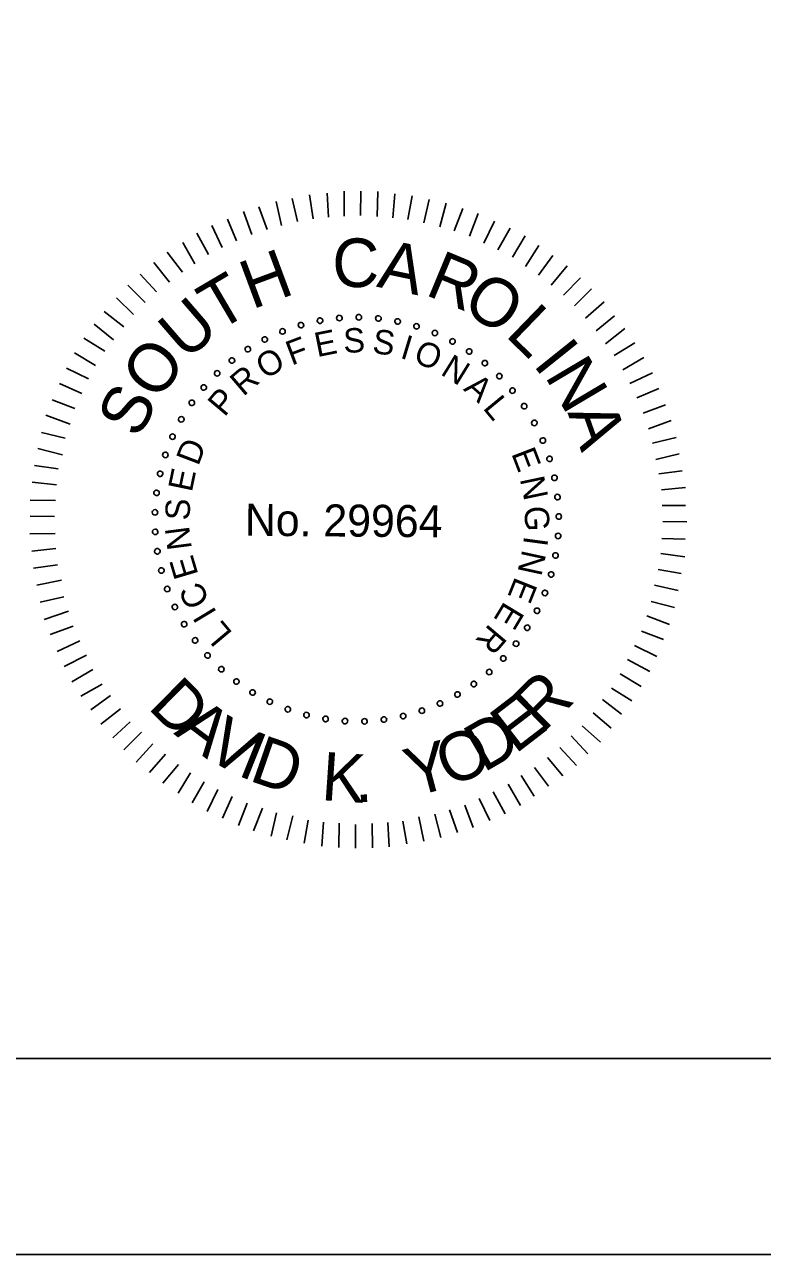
# Model space of a CAD drawing. Extents: x -146.3 to -98.2, y -113.4 to -84.1.
# Drawn here: x -115.032 to -112.521, y -113.391 to -109.207 of the extents above; entities that cross this region are included whole.
import ezdxf

# ---------------------------------------------------------------- set-up
doc = ezdxf.new("R2010")
doc.units = 0
for name, color, linetype in [('BR_BORDER LINES', 7, 'Continuous'), ('BR_TEXT', 7, 'Continuous'), ('Level 31', 7, 'Continuous')]:
    doc.layers.add(name, color=color, linetype=linetype)

msp = doc.modelspace()

# ---------------------------------------------------------------- linework, layer by layer
at = {"layer": 'BR_BORDER LINES'}
msp.add_line((-143.8657, -112.7249), (-98.9787, -112.7249), dxfattribs=at)
at = {"layer": 'BR_TEXT'}
for p, q in [((-114.1028, -109.8773), (-114.1216, -109.7981)), ((-114.0501, -109.8674), (-114.062, -109.7861)), ((-113.9974, -109.8621), (-114.0024, -109.7808)), ((-113.9447, -109.8591), (-113.944, -109.7733)), ((-113.8886, -109.8562), (-113.888, -109.7738)), ((-113.8326, -109.86), (-113.8296, -109.7742)), ((-113.7789, -109.8639), (-113.7725, -109.7827)), ((-113.7274, -109.8701), (-113.713, -109.789)), ((-113.6737, -109.8808), (-113.6548, -109.802)), ((-114.2588, -109.9206), (-114.2867, -109.8426)), ((-114.206, -109.9038), (-114.2351, -109.827)), ((-114.1578, -109.8905), (-114.1754, -109.8092)), ((-113.6189, -109.895), (-113.5976, -109.8139)), ((-113.5699, -109.9091), (-113.5406, -109.8327)), ((-114.3104, -109.9431), (-114.3418, -109.8684)), ((-113.5173, -109.9267), (-113.4881, -109.8491)), ((-113.4695, -109.95), (-113.4323, -109.8759)), ((-114.4058, -109.9892), (-114.4463, -109.9168)), ((-114.3598, -109.9655), (-114.3947, -109.8909)), ((-113.4216, -109.9733), (-113.3798, -109.8993)), ((-113.3715, -109.9977), (-113.3285, -109.926)), ((-114.4529, -110.0208), (-114.4935, -109.9484)), ((-113.3271, -110.0301), (-113.2819, -109.9584)), ((-114.4944, -110.0491), (-114.5464, -109.9812)), ((-113.2827, -110.0591), (-113.2341, -109.992)), ((-114.5393, -110.083), (-114.5925, -110.0162)), ((-113.2395, -110.0938), (-113.1852, -110.0278)), ((-114.6222, -110.1521), (-114.6812, -110.0933)), ((-114.5831, -110.1159), (-114.6386, -110.0559)), ((-113.1975, -110.1273), (-113.1398, -110.0683)), ((-114.6615, -110.193), (-114.7194, -110.1365)), ((-113.16, -110.1642), (-113.1023, -110.1064)), ((-113.1226, -110.2058), (-113.0592, -110.1502)), ((-114.695, -110.2351), (-114.7609, -110.183)), ((-113.0863, -110.2484), (-113.0242, -110.1974)), ((-114.7297, -110.2794), (-114.7956, -110.2262)), ((-113.0547, -110.2933), (-112.989, -110.2412)), ((-114.7586, -110.3181), (-114.8304, -110.274)), ((-113.0253, -110.3324), (-112.9551, -110.2895)), ((-114.7911, -110.367), (-114.8628, -110.3241)), ((-112.9959, -110.3818), (-112.9246, -110.3401)), ((-114.8143, -110.4126), (-114.8895, -110.3754)), ((-114.8376, -110.4616), (-114.914, -110.4278)), ((-112.9723, -110.4278), (-112.8953, -110.3919)), ((-112.9486, -110.4772), (-112.8728, -110.4446)), ((-114.8609, -110.5129), (-114.9385, -110.4837)), ((-112.9262, -110.5289), (-112.8504, -110.5009)), ((-114.8774, -110.5665), (-114.9595, -110.5361)), ((-112.9083, -110.5828), (-112.8314, -110.5537)), ((-114.8938, -110.6145), (-114.9749, -110.5943)), ((-112.895, -110.631), (-112.8147, -110.6122)), ((-114.9034, -110.6705), (-114.9868, -110.6492)), ((-112.884, -110.6871), (-112.8037, -110.6672)), ((-114.9175, -110.7184), (-114.9987, -110.7074)), ((-114.9237, -110.7733), (-115.006, -110.7635)), ((-112.8729, -110.7353), (-112.7939, -110.7256)), ((-112.8643, -110.7903), (-112.7829, -110.7818)), ((-114.9276, -110.8259), (-115.0134, -110.8252)), ((-112.8624, -110.8429), (-112.7823, -110.8436)), ((-114.9303, -110.8807), (-115.0138, -110.88)), ((-112.8594, -110.8978), (-112.7782, -110.8985)), ((-114.9285, -110.938), (-115.0143, -110.9396)), ((-112.8633, -110.955), (-112.7832, -110.958)), ((-114.9255, -110.9895), (-115.0079, -110.9991)), ((-112.8661, -111.0065), (-112.7849, -111.0175)), ((-114.9202, -111.0445), (-115.0016, -111.0564)), ((-114.907, -111.0972), (-114.9906, -111.1148)), ((-112.8756, -111.0613), (-112.7968, -111.0746)), ((-112.8875, -111.1139), (-112.8076, -111.1328)), ((-114.8982, -111.1534), (-114.9797, -111.1721)), ((-112.8994, -111.1699), (-112.8195, -111.19)), ((-114.8826, -111.2027), (-114.9652, -111.2306)), ((-112.9136, -111.2189), (-112.8371, -111.2482)), ((-114.8671, -111.2543), (-114.9451, -111.2823)), ((-114.8446, -111.3037), (-114.9215, -111.3396)), ((-112.9323, -111.2703), (-112.857, -111.2995)), ((-114.8221, -111.3519), (-114.8979, -111.3913)), ((-112.9556, -111.3193), (-112.8804, -111.3565)), ((-112.98, -111.3671), (-112.9037, -111.4078)), ((-114.7996, -111.4013), (-114.872, -111.4431)), ((-113.0045, -111.4162), (-112.9339, -111.4591)), ((-114.768, -111.4508), (-114.8404, -111.4925)), ((-113.0346, -111.4651), (-112.9652, -111.508)), ((-114.7397, -111.4899), (-114.8064, -111.5386)), ((-113.0647, -111.5038), (-112.9999, -111.5535)), ((-114.7058, -111.5348), (-114.7725, -111.5869)), ((-113.0971, -111.5481), (-113.0358, -111.6013)), ((-114.6729, -111.5797), (-114.7318, -111.6342)), ((-113.134, -111.5924), (-113.0716, -111.6479)), ((-114.6343, -111.6144), (-114.6943, -111.6745)), ((-113.1721, -111.6265), (-113.1154, -111.6876)), ((-114.5958, -111.6547), (-114.6523, -111.716)), ((-113.2102, -111.6662), (-113.1535, -111.7284)), ((-114.5525, -111.6894), (-114.6068, -111.7519)), ((-114.5082, -111.7241), (-114.5614, -111.7877)), ((-113.2528, -111.7001), (-113.1996, -111.7635)), ((-114.4672, -111.7531), (-114.509, -111.8225)), ((-113.3414, -111.7624), (-113.2974, -111.8325)), ((-113.2965, -111.7341), (-113.249, -111.7986)), ((-114.4206, -111.7832), (-114.4623, -111.8549)), ((-114.375, -111.8099), (-114.4111, -111.884)), ((-113.3863, -111.7917), (-113.3445, -111.8642)), ((-114.326, -111.8332), (-114.3587, -111.9073)), ((-113.4851, -111.8401), (-113.4491, -111.9148)), ((-113.4368, -111.8176), (-113.3963, -111.8923)), ((-114.2748, -111.8565), (-114.3039, -111.9318)), ((-114.2222, -111.8729), (-114.2526, -111.9505)), ((-114.1743, -111.8894), (-114.1933, -111.9681)), ((-113.6355, -111.8938), (-113.6155, -111.9729)), ((-113.5861, -111.8782), (-113.5581, -111.9562)), ((-113.5333, -111.8626), (-113.5053, -111.9384)), ((-114.1194, -111.8989), (-114.1396, -111.9812)), ((-114.067, -111.9143), (-114.0802, -111.9919)), ((-114.0144, -111.9204), (-114.0208, -112.0028)), ((-113.9618, -111.9243), (-113.9624, -112.0067)), ((-113.9058, -111.9282), (-113.9064, -112.0094)), ((-113.8496, -111.9252), (-113.848, -112.0076)), ((-113.7959, -111.9222), (-113.7908, -112.0047)), ((-113.7443, -111.9169), (-113.7312, -111.9948)), ((-113.6904, -111.9025), (-113.6728, -111.985))]:
    msp.add_line(p, q, dxfattribs=at)
for centre, start, end in [((-114.0913, -110.2294), 16.1422, 196.1422), ((-114.0266, -110.2142), 10.6038, 190.6038), ((-114.0266, -110.2142), 190.6038, 10.6038), ((-113.9607, -110.2052), 5.0653, 185.0653), ((-113.9607, -110.2052), 185.0653, 5.0653), ((-113.8944, -110.2027), 359.5268, 179.5268), ((-113.8944, -110.2027), 179.5268, 359.5268), ((-113.828, -110.2066), 173.9884, 353.9884), ((-113.828, -110.2066), 353.9884, 173.9884), ((-113.7624, -110.2169), 168.4499, 348.4499), ((-113.7624, -110.2169), 348.4499, 168.4499), ((-114.1542, -110.2508), 21.6807, 201.6807), ((-114.1542, -110.2508), 201.6807, 21.6807), ((-114.0913, -110.2294), 196.1422, 16.1422), ((-113.6981, -110.2334), 162.9114, 342.9114), ((-113.6981, -110.2334), 342.9114, 162.9114), ((-113.6356, -110.2561), 157.373, 337.373), ((-113.6356, -110.2561), 337.373, 157.373), ((-114.2723, -110.3113), 32.7576, 212.7576), ((-114.2723, -110.3113), 212.7576, 32.7576), ((-114.2147, -110.2782), 27.2191, 207.2191), ((-114.2147, -110.2782), 207.2191, 27.2191), ((-113.5756, -110.2847), 151.8345, 331.8345), ((-113.5756, -110.2847), 331.8345, 151.8345), ((-114.3264, -110.3498), 38.2961, 218.2961), ((-114.3264, -110.3498), 218.2961, 38.2961), ((-113.5187, -110.319), 146.2961, 326.2961), ((-113.5187, -110.319), 326.2961, 146.2961), ((-114.3766, -110.3933), 43.8345, 223.8345), ((-114.3766, -110.3933), 223.8345, 43.8345), ((-113.4654, -110.3586), 140.7576, 320.7576), ((-113.4654, -110.3586), 320.7576, 140.7576), ((-113.4161, -110.4032), 135.2191, 315.2191), ((-113.4161, -110.4032), 315.2191, 135.2191), ((-114.4224, -110.4415), 49.373, 229.373), ((-114.4224, -110.4415), 229.373, 49.373), ((-113.3714, -110.4523), 129.6807, 309.6807), ((-113.3714, -110.4523), 309.6807, 129.6807), ((-114.4632, -110.4939), 54.9114, 234.9114), ((-114.4632, -110.4939), 234.9114, 54.9114), ((-113.3316, -110.5055), 124.1422, 304.1422), ((-113.3316, -110.5055), 304.1422, 124.1422), ((-114.4989, -110.55), 60.4499, 240.4499), ((-114.4989, -110.55), 240.4499, 60.4499), ((-113.2971, -110.5623), 118.6038, 298.6038), ((-113.2971, -110.5623), 298.6038, 118.6038), ((-114.5289, -110.6092), 65.9884, 245.9884), ((-114.5289, -110.6092), 245.9884, 65.9884), ((-113.2682, -110.6221), 113.0653, 293.0653), ((-113.2682, -110.6221), 293.0653, 113.0653), ((-114.5531, -110.6711), 71.5268, 251.5268), ((-114.5531, -110.6711), 251.5268, 71.5268), ((-113.2453, -110.6845), 107.5268, 287.5268), ((-113.2453, -110.6845), 287.5268, 107.5268), ((-114.5712, -110.735), 77.0653, 257.0653), ((-114.5712, -110.735), 257.0653, 77.0653), ((-113.2285, -110.7488), 101.9884, 281.9884), ((-113.2285, -110.7488), 281.9884, 101.9884), ((-114.5831, -110.8004), 82.6038, 262.6038), ((-114.5831, -110.8004), 262.6038, 82.6038), ((-113.218, -110.8144), 96.4499, 276.4499), ((-113.218, -110.8144), 276.4499, 96.4499), ((-114.5886, -110.8666), 88.1422, 268.1422), ((-114.5886, -110.8666), 268.1422, 88.1422), ((-113.2139, -110.8807), 90.9114, 270.9114), ((-113.2139, -110.8807), 270.9114, 90.9114), ((-114.5877, -110.933), 93.6807, 273.6807), ((-114.5877, -110.933), 273.6807, 93.6807), ((-113.2162, -110.9471), 85.373, 265.373), ((-113.2162, -110.9471), 265.373, 85.373), ((-114.5803, -110.9991), 99.2191, 279.2191), ((-114.5803, -110.9991), 279.2191, 99.2191), ((-113.2249, -111.013), 79.8345, 259.8345), ((-113.2249, -111.013), 259.8345, 79.8345), ((-114.5667, -111.0641), 104.7576, 284.7576), ((-114.5667, -111.0641), 284.7576, 104.7576), ((-113.2399, -111.0777), 74.2961, 254.2961), ((-113.2399, -111.0777), 254.2961, 74.2961), ((-114.5468, -111.1275), 110.2961, 290.2961), ((-114.5468, -111.1275), 290.2961, 110.2961), ((-113.261, -111.1407), 68.7576, 248.7576), ((-113.261, -111.1407), 248.7576, 68.7576), ((-114.5209, -111.1887), 115.8345, 295.8345), ((-114.5209, -111.1887), 295.8345, 115.8345), ((-113.2882, -111.2013), 63.2191, 243.2191), ((-113.2882, -111.2013), 243.2191, 63.2191), ((-114.4892, -111.2471), 121.373, 301.373), ((-114.4892, -111.2471), 301.373, 121.373), ((-113.3211, -111.259), 57.6807, 237.6807), ((-113.3211, -111.259), 237.6807, 57.6807), ((-114.452, -111.3021), 126.9114, 306.9114), ((-114.452, -111.3021), 306.9114, 126.9114), ((-113.3594, -111.3133), 52.1422, 232.1422), ((-113.3594, -111.3133), 232.1422, 52.1422), ((-114.4097, -111.3533), 132.4499, 312.4499), ((-114.4097, -111.3533), 312.4499, 132.4499), ((-114.3626, -111.4002), 137.9884, 317.9884), ((-114.3626, -111.4002), 317.9884, 137.9884), ((-113.4027, -111.3637), 46.6038, 226.6038), ((-113.4027, -111.3637), 226.6038, 46.6038), ((-114.3112, -111.4424), 323.5268, 143.5268), ((-113.4507, -111.4096), 41.0653, 221.0653), ((-113.4507, -111.4096), 221.0653, 41.0653), ((-114.3112, -111.4424), 143.5268, 323.5268), ((-114.256, -111.4793), 149.0653, 329.0653), ((-114.256, -111.4793), 329.0653, 149.0653), ((-113.5589, -111.4865), 29.9884, 209.9884), ((-113.503, -111.4506), 35.5268, 215.5268), ((-113.503, -111.4506), 215.5268, 35.5268), ((-114.1975, -111.5108), 154.6038, 334.6038), ((-114.1975, -111.5108), 334.6038, 154.6038), ((-113.6181, -111.5168), 24.4499, 204.4499), ((-113.6181, -111.5168), 204.4499, 24.4499), ((-113.5589, -111.4865), 209.9884, 29.9884), ((-114.1362, -111.5365), 160.1422, 340.1422), ((-114.1362, -111.5365), 340.1422, 160.1422), ((-114.0728, -111.5561), 165.6807, 345.6807), ((-114.0728, -111.5561), 345.6807, 165.6807), ((-114.0077, -111.5696), 351.2191, 171.2191), ((-113.7437, -111.5595), 13.373, 193.373), ((-113.7437, -111.5595), 193.373, 13.373), ((-113.6798, -111.5412), 18.9114, 198.9114), ((-113.6798, -111.5412), 198.9114, 18.9114), ((-114.0077, -111.5696), 171.2191, 351.2191), ((-113.9417, -111.5767), 356.7576, 176.7576), ((-113.9417, -111.5767), 176.7576, 356.7576), ((-113.8752, -111.5774), 2.2961, 182.2961), ((-113.8752, -111.5774), 182.2961, 2.2961), ((-113.809, -111.5716), 7.8345, 187.8345), ((-113.809, -111.5716), 187.8345, 7.8345)]:
    msp.add_arc(centre, 0.00935, start, end, dxfattribs=at)
at = {"layer": 'Level 31'}
msp.add_lwpolyline([(-146.31, -113.3914), (-98.3112, -113.3914), (-98.3112, -84.0588), (-146.31, -84.0588)], close=True, dxfattribs=at)

# ---------------------------------------------------------------- texts
at = {"layer": 'BR_TEXT'}
for s, height, rotation, p in [('C', 0.1654, 359.5482, (-113.9856, -110.0993)), ('A', 0.1654, 348.1981, (-113.8371, -110.0982)), ('H', 0.1654, 20.3637, (-114.2582, -110.177)), ('R', 0.1654, 337.4344, (-113.6728, -110.1247)), ('T', 0.1654, 30.4992, (-114.3754, -110.2537)), ('O', 0.1652, 326.5869, (-113.5498, -110.1737)), ('U', 0.1654, 40.8022, (-114.4836, -110.3534)), ('L', 0.1654, 315.9488, (-113.3997, -110.2641)), ('E', 0.083, 11.4103, (-114.0363, -110.3386)), ('S', 0.083, 2.208, (-113.9459, -110.324)), ('S', 0.083, 352.6608, (-113.8509, -110.3242)), ('I', 0.083, 343.1136, (-113.7572, -110.3403)), ('O', 0.1654, 52.0267, (-114.583, -110.492)), ('F', 0.083, 20.6127, (-114.1232, -110.3675)), ('O', 0.083, 338.4392, (-113.7126, -110.3538)), ('I', 0.1654, 308.6613, (-113.3045, -110.3631)), ('O', 0.083, 30.8477, (-114.213, -110.4155)), ('N', 0.083, 328.2042, (-113.6198, -110.3956)), ('N', 0.1654, 300.7037, (-113.2637, -110.4023)), ('R', 0.083, 40.3949, (-114.2879, -110.4741)), ('A', 0.083, 318.657, (-113.5412, -110.449)), ('S', 0.1652, 63.2511, (-114.6435, -110.6194)), ('P', 0.083, 49.9421, (-114.352, -110.5442)), ('L', 0.083, 309.4546, (-113.4748, -110.5121)), ('A', 0.1654, 289.4792, (-113.1848, -110.5264)), ('D', 0.083, 69.0364, (-114.4412, -110.7112)), ('E', 0.083, 291.049, (-113.3763, -110.6659)), ('E', 0.083, 78.2388, (-114.4633, -110.8001)), ('N', 0.083, 281.8466, (-113.3467, -110.7526)), ('S', 0.083, 87.786, (-114.4709, -110.8948)), ('No. 29964', 0.10899, 359.5268, (-114.2828, -110.946)), ('G', 0.083, 272.2995, (-113.3311, -110.8463)), ('N', 0.083, 97.3332, (-114.4627, -110.9895)), ('I', 0.083, 262.4084, (-113.3315, -110.9447)), ('E', 0.083, 106.5355, (-114.4401, -111.0782)), ('N', 0.083, 257.7339, (-113.3376, -110.9909)), ('E', 0.083, 248.1867, (-113.3616, -111.0828)), ('C', 0.083, 116.4266, (-114.4002, -111.1682)), ('E', 0.083, 238.9844, (-113.3989, -111.1665)), ('I', 0.083, 121.1011, (-114.3761, -111.2081)), ('L', 0.083, 129.9595, (-114.3219, -111.2776)), ('R', 0.083, 229.782, (-113.4491, -111.2431)), ('D', 0.1647, 315.4053, (-114.6159, -111.5318)), ('R', 0.1647, 44.5947, (-113.2681, -111.6192)), ('E', 0.1647, 37.5339, (-113.3623, -111.691)), ('A', 0.1647, 322.8377, (-114.5271, -111.6193)), ('V', 0.1647, 330.5179, (-114.4243, -111.6969)), ('D', 0.1647, 30.1015, (-113.4701, -111.7536)), ('I', 0.1647, 338.1981, (-114.312, -111.76)), ('D', 0.1647, 340.7995, (-114.2721, -111.7779)), ('Y', 0.1647, 14.8649, (-113.7116, -111.8357)), ('O', 0.1647, 22.4212, (-113.5891, -111.803)), ('K', 0.1647, 356.098, (-114.0251, -111.8454)), ('.', 0.1647, 3.1588, (-113.9069, -111.8538))]:
    msp.add_text(s, height=height, rotation=rotation, dxfattribs=at).set_placement(p)

doc.saveas('drawing.dxf')
